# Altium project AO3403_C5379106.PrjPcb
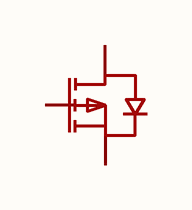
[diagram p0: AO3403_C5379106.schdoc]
1 sheet, 1 parts. Net scope: global (net labels, ports and power ports of the same name join across sheets).

## Sheet AO3403_C5379106.schdoc
size 127 x 101 mm

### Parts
Q?  ao3403_c5379106  [SOT-23-3_L2.9-W1.6-P1.90-LS2.8-BR]  (value not drawn)

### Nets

Not connected (* = marked no-connect by the designer): Q? 1(G) 2(S) 3(D)

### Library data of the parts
Q? = ao3403_c5379106: 数量:1个P沟道;漏源电压(Vdss):30V;连续漏极电流(Id):3A;导通电阻(RDS(on)):85mΩ@10V;耗散功率(Pd):1.56W;阈值电压(Vgs(th)):1.5V;; Manufacturer: MSKSEMI(美森科); ManufacturerPart: AO3403; AddInBom: yes; ModelId: 89cb27a44ab2466697082bb9fd73a7d0; ModelName: SOT-23-3L_L2.9-W1.6-H1.1-LS2.8-P0.95; ModelTransform: 114.173,110.236,0,90,0,0,0,0,0; Number: 1个P沟道; Drain to Source Voltage: 30V; Current - Continuous Drain(Id): 3A; Pd - Power Dissipation: 1.56W; Gate Threshold Voltage (Vgs(th)): 1.5V; Gate Charge(Qg): 2.5nC; Input Capacitance(Ciss): 226pF; Reverse Transfer Capacitance (Crss@Vds): 29pF; Type: P沟道; Output Capacitance(Coss): 39pF; Vgs: ±12V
